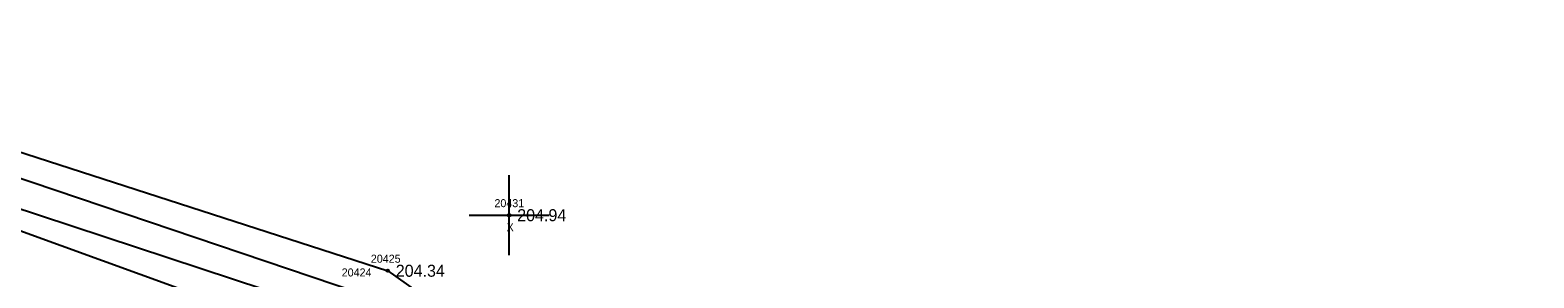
# Model space of a CAD drawing. Extents: x 2260230 to 2261304, y 1064626 to 1065587.
# Drawn here: x 2260697.7 to 2260885.5, y 1065272.4 to 1065303.3 of the extents above; entities that cross this region are included whole.
import ezdxf

# ---------------------------------------------------------------- set-up
doc = ezdxf.new("R2010")
doc.units = 0
for name, color, linetype in [('RD_EX_H2O', 7, 'Continuous'), ('RD_EX_H2O_txCode', 7, 'Continuous'), ('RD_EX_Misc', 7, 'Continuous'), ('RD_EX_Misc_txCode', 7, 'Continuous'), ('RD_EX_TX_H2O_ELEV', 7, 'Continuous'), ('RD_EX_TX_Misc_ELEV', 7, 'Continuous'), ('RD_SMD_Locator', 7, 'Continuous')]:
    doc.layers.add(name, color=color, linetype=linetype)

msp = doc.modelspace()

# ---------------------------------------------------------------- linework, layer by layer
at = {"layer": 'RD_EX_H2O'}
for points in [[(2260649.32, 1065303.35), (2260742.36, 1065273.33), (2260794.49, 1065236.41), (2260847.14, 1065213.75), (2260856.6, 1065227.36), (2260843.65, 1065244.12)], [(2260648.37, 1065301.1), (2260738.72, 1065270.62), (2260793.11, 1065233.68), (2260850.51, 1065208.71), (2260885.55, 1065179.82)], [(2260646.91, 1065297.37), (2260734.94, 1065268.39), (2260788.77, 1065229.77), (2260848.02, 1065204.23), (2260881.52, 1065170.81)], [(2260646.56, 1065296.38), (2260731.62, 1065265.57), (2260787.15, 1065228.1), (2260847.76, 1065200.44), (2260874.83, 1065172.21)]]:
    msp.add_lwpolyline(points, dxfattribs=at)
at = {"layer": 'RD_EX_Misc'}
for p, q in [((2260757.53, 1065275.26), (2260757.53, 1065285.26)), ((2260752.53, 1065280.26), (2260762.53, 1065280.26))]:
    msp.add_line(p, q, dxfattribs=at)
at = {"layer": 'RD_SMD_Locator'}
for centre in [(2260757.53, 1065280.26), (2260742.36, 1065273.33)]:
    msp.add_circle(centre, 0.15, dxfattribs=at)

# ---------------------------------------------------------------- texts
at = {"layer": 'RD_EX_H2O_txCode'}
for s, p in [('20425', (2260740.25, 1065274.33)), ('20424', (2260736.61, 1065272.62))]:
    msp.add_text(s, height=1, dxfattribs=at).set_placement(p)
at = {"layer": 'RD_EX_Misc_txCode'}
for s, p in [('20431', (2260755.69, 1065281.26)), ('X', (2260757.21, 1065278.26))]:
    msp.add_text(s, height=1, dxfattribs=at).set_placement(p)
at = {"layer": 'RD_EX_TX_H2O_ELEV'}
msp.add_text('204.34', height=1.5, dxfattribs=at).set_placement((2260743.36, 1065272.58))
at = {"layer": 'RD_EX_TX_Misc_ELEV'}
msp.add_text('204.94', height=1.5, dxfattribs=at).set_placement((2260758.53, 1065279.51))

doc.saveas('drawing.dxf')
